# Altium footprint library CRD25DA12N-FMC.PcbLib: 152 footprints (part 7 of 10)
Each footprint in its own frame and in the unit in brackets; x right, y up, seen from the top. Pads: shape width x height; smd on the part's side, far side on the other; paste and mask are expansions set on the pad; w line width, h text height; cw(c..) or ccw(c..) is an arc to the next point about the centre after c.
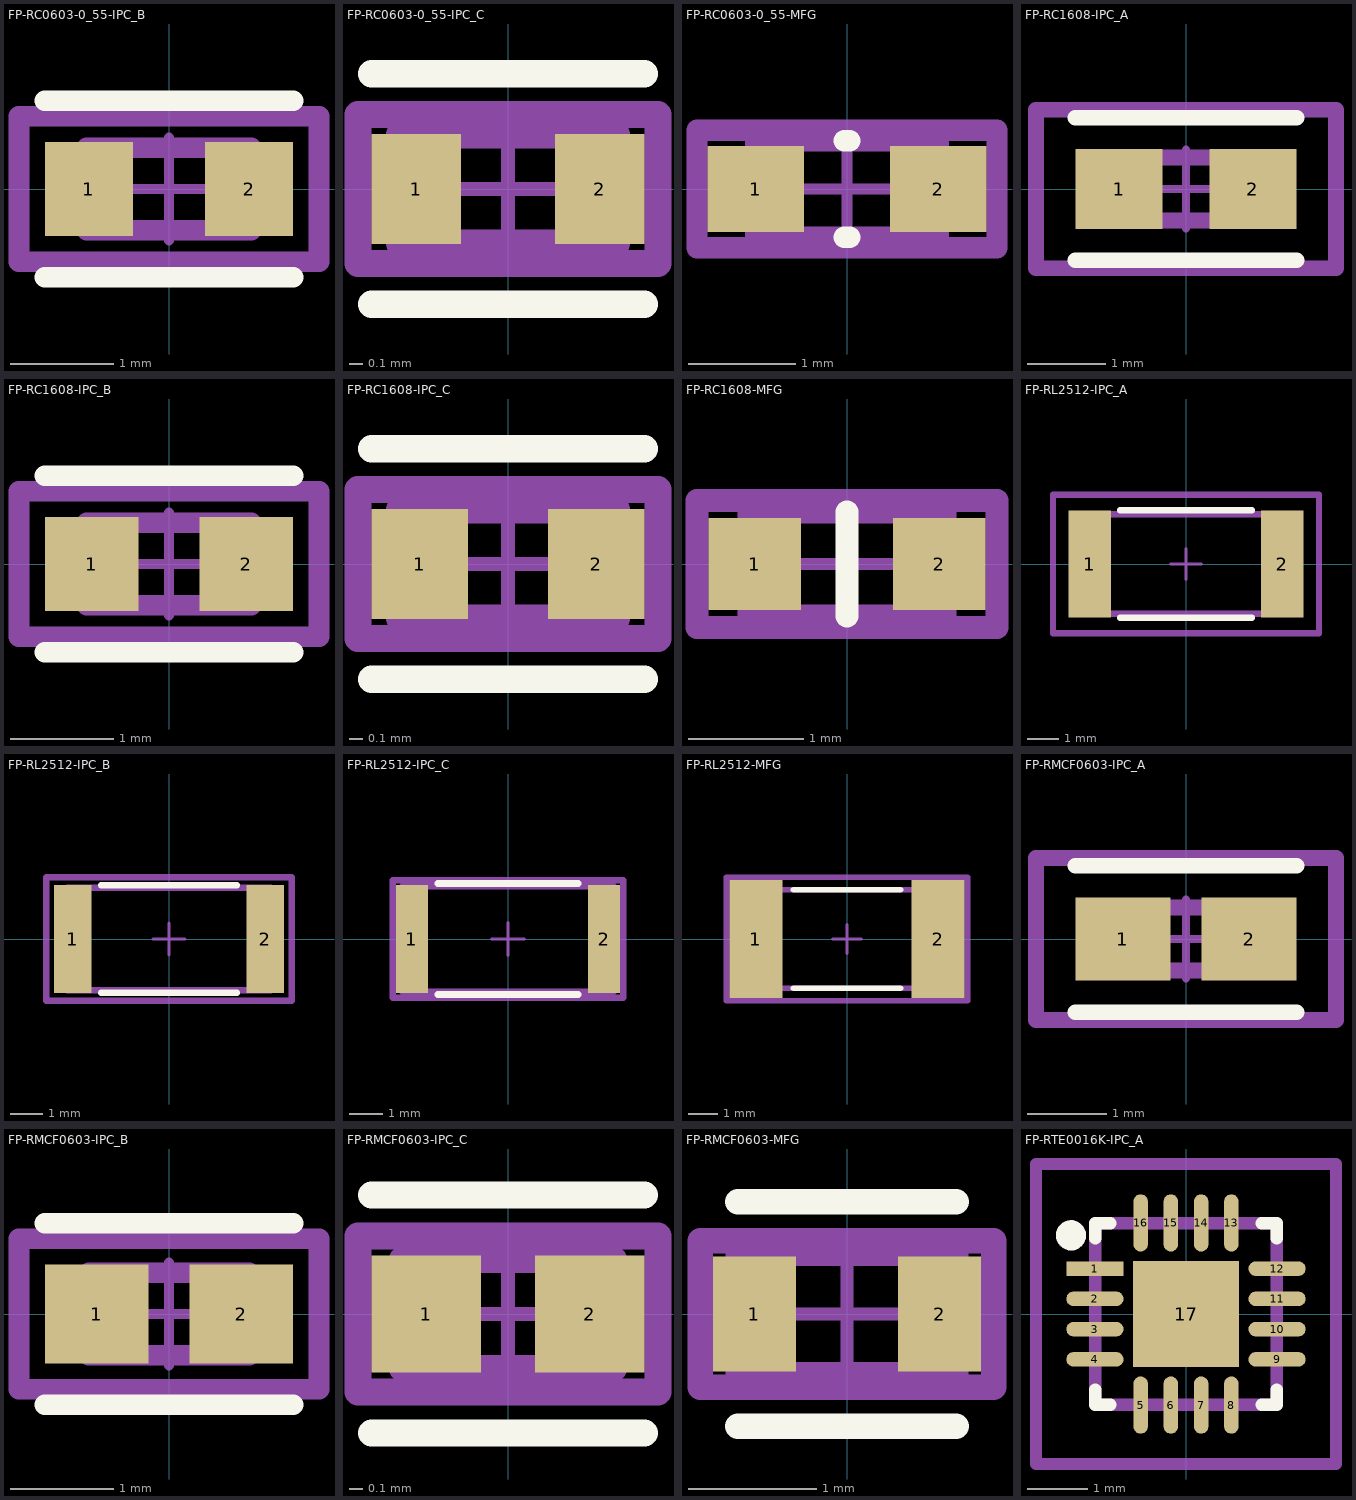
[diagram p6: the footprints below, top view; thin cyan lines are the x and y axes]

## FP-RC0603-0_55-IPC_B [mm]
pads (2):
  rect 0.859x0.912 smd paste+0 mask+0: 1(-0.777,0) 2(0.777,0)
Top Overlay:
  lines w0.2: -1.206,-0.856 1.206,-0.856 ; -1.206,0.856 1.206,0.856
Mechanical 5:
  lines w0.2: -1.456,-0.706 1.456,-0.706 1.456,0.706 -1.456,0.706 -1.456,-0.706
  text ".Designator" at 0,0.188 h1
Mechanical 13:
  lines w0.2: -0.8,-0.4 0.8,-0.4 0.8,0.4 -0.8,0.4 -0.8,-0.4
Mechanical 15:
  lines w0.2: -1.456,-0.706 1.456,-0.706 1.456,0.706 -1.456,0.706 -1.456,-0.706
Mechanical 16:
  lines w0.1: -0.5,0 0.5,0 ; 0,-0.5 0,0.5
3D body "Res_Yageo_RC0603FR-07100KL_eec.STEP": height 0.25, standoff 0, extent -1.456,-0.706 1.456,0.706

## FP-RC0603-0_55-IPC_C [mm]
pads (2):
  rect 0.659x0.812 smd paste+0 mask+0: 1(-0.677,0) 2(0.677,0)
Top Overlay:
  lines w0.2: -1.006,-0.85 1.006,-0.85 ; -1.006,0.85 1.006,0.85
Mechanical 5:
  lines w0.2: -1.106,-0.55 -1.106,0.55 1.106,0.55 1.106,-0.55 -1.106,-0.55
  text ".Designator" at 0,0.188 h1
Mechanical 13:
  lines w0.2: -0.8,-0.4 -0.8,0.4 0.8,0.4 0.8,-0.4 -0.8,-0.4
Mechanical 15:
  lines w0.2: -1.106,-0.55 -1.106,0.55 1.106,0.55 1.106,-0.55 -1.106,-0.55
Mechanical 16:
  lines w0.1: -0.5,0 0.5,0 ; 0,-0.5 0,0.5
3D body "Res_Yageo_RC0603FR-07100KL_eec.STEP": height 0.25, standoff 0, extent -1.106,-0.55 1.106,0.55

## FP-RC0603-0_55-MFG [mm]
pads (2):
  rect 0.9x0.8 smd paste+0 mask+0: 1(-0.85,0) 2(0.85,0)
Top Overlay:
  lines w0.2: -0.025,-0.45 0.025,-0.45 ; -0.025,0.45 0.025,0.45
Mechanical 5:
  lines w0.2: -1.4,-0.55 1.4,-0.55 1.4,0.55 -1.4,0.55 -1.4,-0.55
  text ".Designator" at 0,0.188 h1
Mechanical 13:
  lines w0.2: -0.85,-0.45 0.85,-0.45 0.85,0.45 -0.85,0.45 -0.85,-0.45
Mechanical 15:
  lines w0.2: -1.4,-0.55 1.4,-0.55 1.4,0.55 -1.4,0.55 -1.4,-0.55
Mechanical 16:
  lines w0.1: -0.5,0 0.5,0 ; 0,-0.5 0,0.5
3D body "Res_Yageo_RC0603FR-07100KL_eec.STEP": height 0.25, standoff 0, extent -1.4,-0.55 1.4,0.55

## FP-RC1608-IPC_A [mm]
pads (2):
  rect 1.11x1.012 smd paste+0 mask+0: 1(-0.851,0) 2(0.851,0)
Top Overlay:
  lines w0.2: -1.406,-0.906 1.406,-0.906 ; -1.406,0.906 1.406,0.906
Mechanical 5:
  lines w0.2: -1.906,-1.006 1.906,-1.006 1.906,1.006 -1.906,1.006 -1.906,-1.006
  text ".Designator" at 0,0.188 h1
Mechanical 13:
  lines w0.2: -0.8,-0.4 0.8,-0.4 0.8,0.4 -0.8,0.4 -0.8,-0.4
Mechanical 15:
  lines w0.2: -1.906,-1.006 1.906,-1.006 1.906,1.006 -1.906,1.006 -1.906,-1.006
Mechanical 16:
  lines w0.1: -0.5,0 0.5,0 ; 0,-0.5 0,0.5
3D body "Res_Samsung_RC1608F7873CS_eec.STEP": height 0.25, standoff 0, extent -1.906,-1.006 1.906,1.006

## FP-RC1608-IPC_B [mm]
pads (2):
  rect 0.91x0.912 smd paste+0 mask+0: 1(-0.751,0) 2(0.751,0)
Top Overlay:
  lines w0.2: -1.206,-0.856 1.206,-0.856 ; -1.206,0.856 1.206,0.856
Mechanical 5:
  lines w0.2: -1.456,-0.706 1.456,-0.706 1.456,0.706 -1.456,0.706 -1.456,-0.706
  text ".Designator" at 0,0.188 h1
Mechanical 13:
  lines w0.2: -0.8,-0.4 0.8,-0.4 0.8,0.4 -0.8,0.4 -0.8,-0.4
Mechanical 15:
  lines w0.2: -1.456,-0.706 1.456,-0.706 1.456,0.706 -1.456,0.706 -1.456,-0.706
Mechanical 16:
  lines w0.1: -0.5,0 0.5,0 ; 0,-0.5 0,0.5
3D body "Res_Samsung_RC1608F7873CS_eec.STEP": height 0.25, standoff 0, extent -1.456,-0.706 1.456,0.706

## FP-RC1608-IPC_C [mm]
pads (2):
  rect 0.71x0.812 smd paste+0 mask+0: 1(-0.651,0) 2(0.651,0)
Top Overlay:
  lines w0.2: -1.006,-0.85 1.006,-0.85 ; -1.006,0.85 1.006,0.85
Mechanical 5:
  lines w0.2: -1.106,-0.55 1.106,-0.55 1.106,0.55 -1.106,0.55 -1.106,-0.55
  text ".Designator" at 0,0.188 h1
Mechanical 13:
  lines w0.2: -0.8,-0.4 0.8,-0.4 0.8,0.4 -0.8,0.4 -0.8,-0.4
Mechanical 15:
  lines w0.2: -1.106,-0.55 1.106,-0.55 1.106,0.55 -1.106,0.55 -1.106,-0.55
Mechanical 16:
  lines w0.1: -0.5,0 0.5,0 ; 0,-0.5 0,0.5
3D body "Res_Samsung_RC1608F7873CS_eec.STEP": height 0.25, standoff 0, extent -1.106,-0.55 1.106,0.55

## FP-RC1608-MFG [mm]
pads (2):
  rect 0.8x0.8 smd paste+0 mask+0: 1(-0.8,0) 2(0.8,0)
Top Overlay:
  lines w0.2: 0,-0.45 0,0.45
Mechanical 5:
  lines w0.2: -1.3,-0.55 1.3,-0.55 1.3,0.55 -1.3,0.55 -1.3,-0.55
  text ".Designator" at 0,0 h1
Mechanical 13:
  lines w0.2: -0.85,-0.45 0.85,-0.45 0.85,0.45 -0.85,0.45 -0.85,-0.45
Mechanical 15:
  lines w0.2: -1.3,-0.55 1.3,-0.55 1.3,0.55 -1.3,0.55 -1.3,-0.55
Mechanical 16:
  lines w0.1: -0.5,0 0.5,0 ; 0,-0.5 0,0.5
3D body "Res_Samsung_RC1608F7873CS_eec.STEP": height 0.25, standoff 0, extent -1.3,-0.55 1.3,0.55

## FP-RL2512-IPC_A [mm]
pads (2):
  rect 1.358x3.458 smd paste+0 mask+0: 1(-3.102,0) 2(3.102,0)
Top Overlay:
  lines w0.2: -2.123,-1.729 2.123,-1.729 ; -2.123,1.729 2.123,1.729
Mechanical 5:
  lines w0.2: -4.281,-2.229 -4.281,2.229 4.281,2.229 4.281,-2.229 -4.281,-2.229
  text ".Designator" at 0,0.188 h1
Mechanical 13:
  lines w0.2: -3.175,-1.6 -3.175,1.6 3.175,1.6 3.175,-1.6 -3.175,-1.6
Mechanical 15:
  lines w0.2: -4.281,-2.229 -4.281,2.229 4.281,2.229 4.281,-2.229 -4.281,-2.229
Mechanical 16:
  lines w0.1: -0.5,0 0.5,0 ; 0,-0.5 0,0.5
3D body "Res_YAGEO_RL2512FK-070R1L_eec.STEP": height 0.25, standoff 0, extent -4.281,-2.229 4.281,2.229

## FP-RL2512-IPC_B [mm]
pads (2):
  rect 1.158x3.358 smd paste+0 mask+0: 1(-3.002,0) 2(3.002,0)
Top Overlay:
  lines w0.2: -2.123,-1.679 2.123,-1.679 ; -2.123,1.679 2.123,1.679
Mechanical 5:
  lines w0.2: -3.831,-1.929 -3.831,1.929 3.831,1.929 3.831,-1.929 -3.831,-1.929
  text ".Designator" at 0,0.188 h1
Mechanical 13:
  lines w0.2: -3.175,-1.6 -3.175,1.6 3.175,1.6 3.175,-1.6 -3.175,-1.6
Mechanical 15:
  lines w0.2: -3.831,-1.929 -3.831,1.929 3.831,1.929 3.831,-1.929 -3.831,-1.929
Mechanical 16:
  lines w0.1: -0.5,0 0.5,0 ; 0,-0.5 0,0.5
3D body "Res_YAGEO_RL2512FK-070R1L_eec.STEP": height 0.25, standoff 0, extent -3.831,-1.929 3.831,1.929

## FP-RL2512-IPC_C [mm]
pads (2):
  rect 0.958x3.258 smd paste+0 mask+0: 1(-2.902,0) 2(2.902,0)
Top Overlay:
  lines w0.2: -2.123,-1.675 2.123,-1.675 ; -2.123,1.675 2.123,1.675
Mechanical 5:
  lines w0.2: -3.481,-1.775 3.481,-1.775 3.481,1.775 -3.481,1.775 -3.481,-1.775
  text ".Designator" at 0,0.188 h1
Mechanical 13:
  lines w0.2: -3.175,-1.6 3.175,-1.6 3.175,1.6 -3.175,1.6 -3.175,-1.6
Mechanical 15:
  lines w0.2: -3.481,-1.775 3.481,-1.775 3.481,1.775 -3.481,1.775 -3.481,-1.775
Mechanical 16:
  lines w0.1: -0.5,0 0.5,0 ; 0,-0.5 0,0.5
3D body "Res_YAGEO_RL2512FK-070R1L_eec.STEP": height 0.25, standoff 0, extent -3.481,-1.775 3.481,1.775

## FP-RL2512-MFG [mm]
pads (2):
  rect 1.8x4 smd paste+0 mask+0: 1(-3.1,0) 2(3.1,0)
Top Overlay:
  lines w0.2: -1.825,-1.675 1.825,-1.675 ; -1.825,1.675 1.825,1.675
Mechanical 5:
  lines w0.2: -4.1,-2.1 4.1,-2.1 4.1,2.1 -4.1,2.1 -4.1,-2.1
  text ".Designator" at 0,0.188 h1
Mechanical 13:
  lines w0.2: -3.225,-1.675 3.225,-1.675 3.225,1.675 -3.225,1.675 -3.225,-1.675
Mechanical 15:
  lines w0.2: -4.1,-2.1 4.1,-2.1 4.1,2.1 -4.1,2.1 -4.1,-2.1
Mechanical 16:
  lines w0.1: -0.5,0 0.5,0 ; 0,-0.5 0,0.5
3D body "Res_YAGEO_RL2512FK-070R1L_eec.STEP": height 0.25, standoff 0, extent -4.1,-2.1 4.1,2.1

## FP-RMCF0603-IPC_A [mm]
pads (2):
  rect 1.206x1.058 smd paste+0 mask+0: 1(-0.801,0) 2(0.801,0)
Top Overlay:
  lines w0.2: -1.404,-0.929 1.404,-0.929 ; -1.404,0.929 1.404,0.929
Mechanical 5:
  lines w0.2: -1.904,-1.029 1.904,-1.029 1.904,1.029 -1.904,1.029 -1.904,-1.029
  text ".Designator" at 0,0.188 h1
Mechanical 13:
  lines w0.2: -0.775,-0.4 0.775,-0.4 0.775,0.4 -0.775,0.4 -0.775,-0.4
Mechanical 15:
  lines w0.2: -1.904,-1.029 1.904,-1.029 1.904,1.029 -1.904,1.029 -1.904,-1.029
Mechanical 16:
  lines w0.1: -0.5,0 0.5,0 ; 0,-0.5 0,0.5
3D body "Res_Stackpole_Electronics_RMCF0603JT1M80_eec.STEP": height 0.25, standoff 0, extent -1.904,-1.029 1.904,1.029

## FP-RMCF0603-IPC_B [mm]
pads (2):
  rect 1.006x0.958 smd paste+0 mask+0: 1(-0.701,0) 2(0.701,0)
Top Overlay:
  lines w0.2: -1.204,-0.879 1.204,-0.879 ; -1.204,0.879 1.204,0.879
Mechanical 5:
  lines w0.2: -1.454,-0.729 1.454,-0.729 1.454,0.729 -1.454,0.729 -1.454,-0.729
  text ".Designator" at 0,0.188 h1
Mechanical 13:
  lines w0.2: -0.775,-0.4 0.775,-0.4 0.775,0.4 -0.775,0.4 -0.775,-0.4
Mechanical 15:
  lines w0.2: -1.454,-0.729 1.454,-0.729 1.454,0.729 -1.454,0.729 -1.454,-0.729
Mechanical 16:
  lines w0.1: -0.5,0 0.5,0 ; 0,-0.5 0,0.5
3D body "Res_Stackpole_Electronics_RMCF0603JT1M80_eec.STEP": height 0.25, standoff 0, extent -1.454,-0.729 1.454,0.729

## FP-RMCF0603-IPC_C [mm]
pads (2):
  rect 0.806x0.858 smd paste+0 mask+0: 1(-0.601,0) 2(0.601,0)
Top Overlay:
  lines w0.2: -1.004,-0.875 1.004,-0.875 ; -1.004,0.875 1.004,0.875
Mechanical 5:
  lines w0.2: -1.104,-0.575 1.104,-0.575 1.104,0.575 -1.104,0.575 -1.104,-0.575
  text ".Designator" at 0,0.188 h1
Mechanical 13:
  lines w0.2: -0.775,-0.4 0.775,-0.4 0.775,0.4 -0.775,0.4 -0.775,-0.4
Mechanical 15:
  lines w0.2: -1.104,-0.575 1.104,-0.575 1.104,0.575 -1.104,0.575 -1.104,-0.575
Mechanical 16:
  lines w0.1: -0.5,0 0.5,0 ; 0,-0.5 0,0.5
3D body "Res_Stackpole_Electronics_RMCF0603JT1M80_eec.STEP": height 0.25, standoff 0, extent -1.104,-0.575 1.104,0.575

## FP-RMCF0603-MFG [mm]
pads (2):
  rect 0.65x0.9 smd paste+0 mask+0: 1(-0.725,0) 2(0.725,0)
Top Overlay:
  lines w0.2: -0.854,-0.879 0.854,-0.879 ; -0.854,0.879 0.854,0.879
Mechanical 5:
  lines w0.2: -1.15,-0.575 -1.15,0.575 1.15,0.575 1.15,-0.575 -1.15,-0.575
  text ".Designator" at 0,0.188 h1
Mechanical 13:
  lines w0.2: -0.85,-0.475 -0.85,0.475 0.85,0.475 0.85,-0.475 -0.85,-0.475
Mechanical 15:
  lines w0.2: -1.15,-0.575 -1.15,0.575 1.15,0.575 1.15,-0.575 -1.15,-0.575
Mechanical 16:
  lines w0.1: -0.5,0 0.5,0 ; 0,-0.5 0,0.5
3D body "Res_Stackpole_Electronics_RMCF0603JT1M80_eec.STEP": height 0.25, standoff 0, extent -1.15,-0.575 1.15,0.575

## FP-RTE0016K-IPC_A [mm]
pads (17):
  rect 0.949x0.239 smd paste+0 mask+0: 1(-1.505,0.75)
  rrect100% 0.949x0.239 smd paste+0 mask+0: 2(-1.505,0.25) 3(-1.505,-0.25) 4(-1.505,-0.75) 9(1.505,-0.75) 10(1.505,-0.25) 11(1.505,0.25) 12(1.505,0.75)
  rrect100% 0.239x0.949 smd paste+0 mask+0: 5(-0.75,-1.505) 6(-0.25,-1.505) 7(0.25,-1.505) 8(0.75,-1.505) 13(0.75,1.505) 14(0.25,1.505) 15(-0.25,1.505) 16(-0.75,1.505)
  rect 1.76x1.76 smd paste-1000 mask+0: 17(0,0)
Top Overlay:
  circle w0.25: c-1.9,1.3 r0.125
  lines w0.2: -1.5,-1.245 -1.5,-1.5 -1.245,-1.5 ; -1.5,1.245 -1.5,1.5 -1.245,1.5 ; 1.245,-1.5 1.5,-1.5 1.5,-1.245 ; 1.245,1.5 1.5,1.5 1.5,1.245
Top Paste:
  rectangle: -0.557,-0.557 0.557,0.557
Mechanical 5:
  lines w0.2: -2.479,-2.479 2.479,-2.479 2.479,2.479 -2.479,2.479 -2.479,-2.479
  text ".Designator" at 0,0.188 h1
Mechanical 13:
  lines w0.2: -1.5,-1.5 1.5,-1.5 1.5,1.5 -1.5,1.5 -1.5,-1.5
Mechanical 15:
  lines w0.2: -2.479,-2.479 2.479,-2.479 2.479,2.479 -2.479,2.479 -2.479,-2.479
Mechanical 16:
  lines w0.1: -0.5,0 0.5,0 ; 0,-0.5 0,0.5
3D body "IC_Texas_Instruments_LM51571QRTERQ1_eec.STEP": height 0.25, standoff 0, extent -2.479,-2.479 2.479,2.479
